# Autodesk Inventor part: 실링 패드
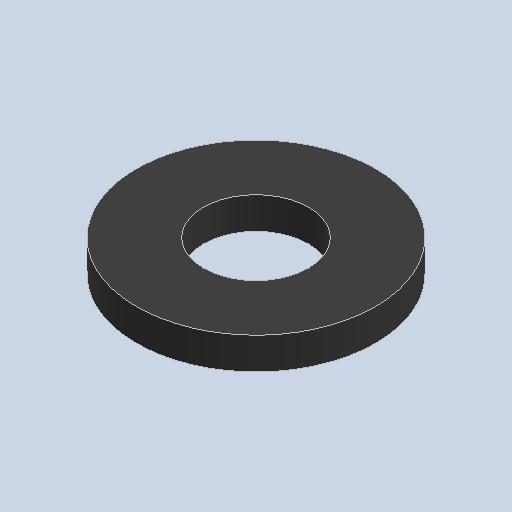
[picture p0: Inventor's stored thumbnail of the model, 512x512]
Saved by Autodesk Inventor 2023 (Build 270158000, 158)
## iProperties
Created: 2024-09
Part Number: 실링 패드
Material: 고무
Document SubType Name: Modeling
Designer: home
Density: 0.93 g/cm^3
Appearance: 기본값
Author: jhkim
Sending System: Autodesk Inventor 2025
Preprocessor: ST-DEVELOPER v20
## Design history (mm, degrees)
feature "솔리드1"
node "솔리드2"
